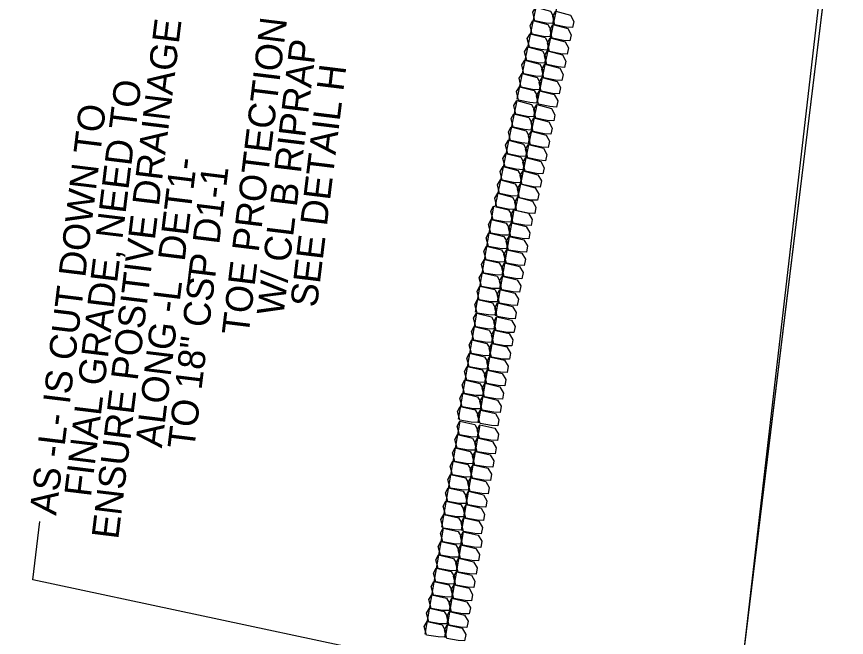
# Model space of a CAD drawing. Extents: x 465700 to 483515, y 488970 to 507540.
# Drawn here: x 481134.4 to 481288.8, y 490580.8 to 490696.3 of the extents above; entities that cross this region are included whole.
import ezdxf

# ---------------------------------------------------------------- set-up
doc = ezdxf.new("R2010")
doc.units = 0
for name, color, linetype in [('Exist Plan Preparation Watershed Blue', 7, 'Continuous'), ('Prop Earthen Structure Base Ditch Lateral Detail Label', 7, 'Continuous'), ('Prop Erosion Embankment Toe Protection CELL', 7, 'Continuous'), ('Prop Erosion Embankment Toe Protection Label', 7, 'Continuous'), ('Prop NEU Channel Block Detail Label', 7, 'Continuous')]:
    doc.layers.add(name, color=color, linetype=linetype)

msp = doc.modelspace()

# ---------------------------------------------------------------- linework, layer by layer
at = {"layer": 'Exist Plan Preparation Watershed Blue'}
for points in [[(481178.35, 489921.07), (481181.18, 489944.23), (481192.1, 489942.89), (481199.42, 490002.85), (481223.67, 490201.37), (481232.65, 490274.58), (481301.55, 490839.02), (481357.88, 490832.14), (481339.74, 490683.62), (481315.49, 490485.09), (481303.36, 490385.83), (481279.12, 490187.3), (481254.87, 489988.78), (481242.75, 489889.52)], [(480982.54, 490200.49), (481022.64, 490226.93), (481057.88, 490239.62), (481085.68, 490250.52), (481125.08, 490261.61), (481159, 490262.25), (481229.67, 490258.2), (481254.1, 490443.2), (481288.29, 490738.89), (481339.74, 490683.62), (481381.2, 490650.46), (481429.31, 490629.05), (481609.7, 490592.3), (481802.24, 490660.02), (481819.54, 490679.79), (481842.61, 490718.46), (481669.68, 490775.55), (481613.6, 490791.65)]]:
    msp.add_lwpolyline(points, dxfattribs=at)
msp.add_lwpolyline([(481259, 490360.8), (481243.71, 490365.51), (481284.29, 490697.69), (481301.55, 490839.02), (481323.3, 490836.37), (481281, 490489.23), (481265.22, 490360.1)], close=True, dxfattribs=at)
at = {"layer": 'Prop Erosion Embankment Toe Protection CELL'}
for p, q in [((481231.47, 490700.49), (481227.46, 490680.9)), ((481235.19, 490699.73), (481231.18, 490680.14)), ((481227.43, 490680.68), (481223.42, 490661.08)), ((481231.15, 490679.92), (481227.14, 490660.32)), ((481223.13, 490661.01), (481219.72, 490641.3)), ((481226.87, 490660.36), (481223.47, 490640.65)), ((481219.94, 490641.09), (481216.53, 490621.38)), ((481223.68, 490640.44), (481220.28, 490620.73)), ((481216.85, 490621.01), (481213.44, 490601.3)), ((481220.59, 490620.36), (481217.19, 490600.66)), ((481213.75, 490601.11), (481210.35, 490581.4)), ((481217.5, 490600.46), (481214.1, 490580.75))]:
    msp.add_line(p, q, dxfattribs=at)
for points in [[(481234.12, 490695), (481232.91, 490695.07), (481230.8, 490695.5), (481230.42, 490697.14), (481230.97, 490698.04), (481233.72, 490697.3), (481234.35, 490696.13), (481234.12, 490695)], [(481237.84, 490694.24), (481236.63, 490694.31), (481234.53, 490694.74), (481234.15, 490696.37), (481234.69, 490697.28), (481237.45, 490696.54), (481238.07, 490695.37), (481237.84, 490694.24)], [(481233.62, 490692.53), (481232.41, 490692.6), (481230.3, 490693.03), (481229.92, 490694.66), (481230.46, 490695.57), (481233.22, 490694.83), (481233.85, 490693.68), (481233.62, 490692.53)], [(481237.34, 490691.77), (481236.13, 490691.84), (481234.02, 490692.27), (481233.64, 490693.9), (481234.18, 490694.81), (481236.94, 490694.07), (481237.57, 490692.92), (481237.34, 490691.77)], [(481233.11, 490690.05), (481231.9, 490690.15), (481229.8, 490690.58), (481229.41, 490692.19), (481229.96, 490693.1), (481232.72, 490692.38), (481233.35, 490691.23), (481233.11, 490690.05)], [(481236.83, 490689.29), (481235.63, 490689.39), (481233.52, 490689.82), (481233.14, 490691.43), (481233.68, 490692.34), (481236.44, 490691.62), (481237.07, 490690.47), (481236.83, 490689.29)], [(481232.61, 490687.6), (481231.4, 490687.7), (481229.3, 490688.13), (481228.91, 490689.74), (481229.45, 490690.65), (481232.22, 490689.93), (481232.84, 490688.76), (481232.61, 490687.6)], [(481236.33, 490686.84), (481235.13, 490686.94), (481233.02, 490687.37), (481232.63, 490688.98), (481233.18, 490689.89), (481235.94, 490689.17), (481236.57, 490687.99), (481236.33, 490686.84)], [(481232.11, 490685.15), (481230.9, 490685.22), (481228.79, 490685.65), (481228.41, 490687.29), (481228.95, 490688.2), (481231.71, 490687.46), (481232.34, 490686.28), (481232.11, 490685.15)], [(481235.83, 490684.39), (481234.62, 490684.46), (481232.51, 490684.89), (481232.13, 490686.53), (481232.68, 490687.44), (481235.43, 490686.69), (481236.06, 490685.52), (481235.83, 490684.39)], [(481231.6, 490682.68), (481230.39, 490682.75), (481228.29, 490683.18), (481227.91, 490684.81), (481228.45, 490685.72), (481231.21, 490684.98), (481231.84, 490683.83), (481231.6, 490682.68)], [(481235.33, 490681.92), (481234.12, 490681.99), (481232.01, 490682.42), (481231.63, 490684.05), (481232.17, 490684.96), (481234.93, 490684.22), (481235.56, 490683.07), (481235.33, 490681.92)], [(481231.1, 490680.21), (481229.89, 490680.3), (481227.78, 490680.73), (481227.4, 490682.34), (481227.94, 490683.25), (481230.7, 490682.53), (481231.34, 490681.38), (481231.1, 490680.21)], [(481234.82, 490679.45), (481233.61, 490679.54), (481231.51, 490679.97), (481231.12, 490681.58), (481231.67, 490682.49), (481234.43, 490681.77), (481235.06, 490680.62), (481234.82, 490679.45)], [(481230.58, 490677.64), (481229.38, 490677.73), (481227.27, 490678.16), (481226.88, 490679.77), (481227.43, 490680.68), (481230.19, 490679.96), (481230.82, 490678.79), (481230.58, 490677.64)], [(481234.31, 490676.87), (481233.1, 490676.97), (481230.99, 490677.4), (481230.61, 490679.01), (481231.15, 490679.92), (481233.91, 490679.2), (481234.54, 490678.03), (481234.31, 490676.87)], [(481230.08, 490675.19), (481228.87, 490675.26), (481226.76, 490675.69), (481226.38, 490677.32), (481226.93, 490678.23), (481229.68, 490677.49), (481230.31, 490676.31), (481230.08, 490675.19)], [(481233.8, 490674.43), (481232.59, 490674.49), (481230.49, 490674.92), (481230.11, 490676.56), (481230.65, 490677.47), (481233.41, 490676.73), (481234.03, 490675.55), (481233.8, 490674.43)], [(481229.58, 490672.71), (481228.37, 490672.78), (481226.26, 490673.21), (481225.88, 490674.85), (481226.42, 490675.76), (481229.18, 490675.01), (481229.81, 490673.86), (481229.58, 490672.71)], [(481233.3, 490671.95), (481232.09, 490672.02), (481229.98, 490672.45), (481229.6, 490674.09), (481230.14, 490675), (481232.9, 490674.25), (481233.53, 490673.1), (481233.3, 490671.95)], [(481229.07, 490670.24), (481227.86, 490670.33), (481225.76, 490670.76), (481225.37, 490672.37), (481225.92, 490673.28), (481228.68, 490672.56), (481229.31, 490671.41), (481229.07, 490670.24)], [(481232.79, 490669.48), (481231.59, 490669.57), (481229.48, 490670), (481229.1, 490671.61), (481229.64, 490672.52), (481232.4, 490671.8), (481233.03, 490670.65), (481232.79, 490669.48)], [(481228.57, 490667.79), (481227.36, 490667.88), (481225.26, 490668.31), (481224.87, 490669.92), (481225.41, 490670.83), (481228.18, 490670.12), (481228.8, 490668.94), (481228.57, 490667.79)], [(481232.29, 490667.03), (481231.09, 490667.12), (481228.98, 490667.55), (481228.59, 490669.16), (481229.14, 490670.07), (481231.9, 490669.35), (481232.53, 490668.18), (481232.29, 490667.03)], [(481228.07, 490665.34), (481226.86, 490665.41), (481224.75, 490665.84), (481224.37, 490667.47), (481224.91, 490668.38), (481227.67, 490667.64), (481228.3, 490666.47), (481228.07, 490665.34)], [(481231.79, 490664.58), (481230.58, 490664.65), (481228.47, 490665.08), (481228.09, 490666.71), (481228.64, 490667.62), (481231.39, 490666.88), (481232.02, 490665.71), (481231.79, 490664.58)], [(481227.56, 490662.87), (481226.35, 490662.94), (481224.25, 490663.37), (481223.87, 490665), (481224.41, 490665.91), (481227.17, 490665.17), (481227.8, 490664.02), (481227.56, 490662.87)], [(481231.29, 490662.11), (481230.08, 490662.17), (481227.97, 490662.6), (481227.59, 490664.24), (481228.13, 490665.15), (481230.89, 490664.41), (481231.52, 490663.26), (481231.29, 490662.11)], [(481227.06, 490660.39), (481225.85, 490660.49), (481223.74, 490660.92), (481223.36, 490662.53), (481223.9, 490663.44), (481226.66, 490662.72), (481227.3, 490661.57), (481227.06, 490660.39)], [(481230.78, 490659.63), (481229.57, 490659.72), (481227.47, 490660.16), (481227.08, 490661.77), (481227.63, 490662.67), (481230.39, 490661.96), (481231.02, 490660.81), (481230.78, 490659.63)], [(481226.37, 490658.06), (481225.16, 490658.12), (481223.05, 490658.48), (481222.61, 490660.08), (481223.13, 490661.01), (481225.91, 490660.37), (481226.57, 490659.22), (481226.37, 490658.06)], [(481230.12, 490657.42), (481228.91, 490657.47), (481226.79, 490657.84), (481226.36, 490659.44), (481226.87, 490660.36), (481229.65, 490659.73), (481230.32, 490658.57), (481230.12, 490657.42)], [(481225.95, 490655.6), (481224.73, 490655.63), (481222.62, 490656), (481222.19, 490657.62), (481222.7, 490658.54), (481225.48, 490657.89), (481226.14, 490656.73), (481225.95, 490655.6)], [(481229.69, 490654.95), (481228.48, 490654.98), (481226.36, 490655.35), (481225.93, 490656.97), (481226.44, 490657.9), (481229.22, 490657.24), (481229.89, 490656.09), (481229.69, 490654.95)], [(481225.52, 490653.11), (481224.3, 490653.14), (481222.19, 490653.51), (481221.76, 490655.13), (481222.27, 490656.06), (481225.05, 490655.4), (481225.72, 490654.27), (481225.52, 490653.11)], [(481229.26, 490652.46), (481228.05, 490652.5), (481225.93, 490652.86), (481225.5, 490654.48), (481226.02, 490655.41), (481228.79, 490654.75), (481229.46, 490653.62), (481229.26, 490652.46)], [(481225.09, 490650.62), (481223.88, 490650.68), (481221.76, 490651.04), (481221.33, 490652.64), (481221.84, 490653.57), (481224.62, 490652.93), (481225.29, 490651.8), (481225.09, 490650.62)], [(481228.83, 490649.98), (481227.62, 490650.03), (481225.51, 490650.4), (481225.07, 490652), (481225.59, 490652.92), (481228.37, 490652.29), (481229.04, 490651.16), (481228.83, 490649.98)], [(481224.66, 490648.16), (481223.45, 490648.22), (481221.34, 490648.58), (481220.9, 490650.18), (481221.42, 490651.1), (481224.2, 490650.47), (481224.86, 490649.32), (481224.66, 490648.16)], [(481228.41, 490647.51), (481227.2, 490647.57), (481225.08, 490647.93), (481224.65, 490649.53), (481225.16, 490650.46), (481227.94, 490649.82), (481228.61, 490648.67), (481228.41, 490647.51)], [(481224.24, 490645.7), (481223.02, 490645.73), (481220.91, 490646.09), (481220.48, 490647.71), (481220.99, 490648.64), (481223.77, 490647.98), (481224.43, 490646.83), (481224.24, 490645.7)], [(481227.98, 490645.05), (481226.77, 490645.08), (481224.65, 490645.45), (481224.22, 490647.07), (481224.73, 490647.99), (481227.51, 490647.34), (481228.18, 490646.18), (481227.98, 490645.05)], [(481223.81, 490643.21), (481222.59, 490643.24), (481220.48, 490643.6), (481220.05, 490645.23), (481220.56, 490646.15), (481223.34, 490645.5), (481224.01, 490644.36), (481223.81, 490643.21)], [(481227.55, 490642.56), (481226.34, 490642.59), (481224.22, 490642.96), (481223.79, 490644.58), (481224.3, 490645.51), (481227.08, 490644.85), (481227.75, 490643.72), (481227.55, 490642.56)], [(481223.38, 490640.72), (481222.17, 490640.78), (481220.05, 490641.14), (481219.62, 490642.74), (481220.13, 490643.66), (481222.91, 490643.03), (481223.58, 490641.9), (481223.38, 490640.72)], [(481227.12, 490640.07), (481225.91, 490640.13), (481223.79, 490640.49), (481223.36, 490642.09), (481223.88, 490643.02), (481226.66, 490642.38), (481227.33, 490641.25), (481227.12, 490640.07)], [(481223.18, 490638.14), (481221.97, 490638.2), (481219.86, 490638.56), (481219.42, 490640.16), (481219.94, 490641.09), (481222.72, 490640.45), (481223.38, 490639.3), (481223.18, 490638.14)], [(481226.93, 490637.5), (481225.72, 490637.55), (481223.6, 490637.92), (481223.17, 490639.51), (481223.68, 490640.44), (481226.46, 490639.81), (481227.13, 490638.65), (481226.93, 490637.5)], [(481222.76, 490635.68), (481221.54, 490635.71), (481219.43, 490636.08), (481219, 490637.7), (481219.51, 490638.62), (481222.29, 490637.97), (481222.95, 490636.81), (481222.76, 490635.68)], [(481226.5, 490635.03), (481225.29, 490635.06), (481223.17, 490635.43), (481222.74, 490637.05), (481223.26, 490637.98), (481226.03, 490637.32), (481226.7, 490636.16), (481226.5, 490635.03)], [(481222.33, 490633.19), (481221.11, 490633.22), (481219, 490633.59), (481218.57, 490635.21), (481219.08, 490636.14), (481221.86, 490635.48), (481222.53, 490634.35), (481222.33, 490633.19)], [(481226.07, 490632.54), (481224.86, 490632.58), (481222.74, 490632.94), (481222.31, 490634.56), (481222.83, 490635.49), (481225.6, 490634.83), (481226.27, 490633.7), (481226.07, 490632.54)], [(481221.9, 490630.7), (481220.69, 490630.76), (481218.57, 490631.12), (481218.14, 490632.72), (481218.65, 490633.65), (481221.43, 490633.01), (481222.1, 490631.88), (481221.9, 490630.7)], [(481225.64, 490630.06), (481224.43, 490630.11), (481222.32, 490630.48), (481221.88, 490632.07), (481222.4, 490633), (481225.18, 490632.37), (481225.85, 490631.24), (481225.64, 490630.06)], [(481221.47, 490628.24), (481220.26, 490628.29), (481218.15, 490628.66), (481217.71, 490630.26), (481218.23, 490631.18), (481221.01, 490630.55), (481221.67, 490629.4), (481221.47, 490628.24)], [(481225.22, 490627.59), (481224.01, 490627.65), (481221.89, 490628.01), (481221.46, 490629.61), (481221.97, 490630.54), (481224.75, 490629.9), (481225.42, 490628.75), (481225.22, 490627.59)], [(481221.05, 490625.77), (481219.83, 490625.81), (481217.72, 490626.17), (481217.29, 490627.79), (481217.8, 490628.72), (481220.58, 490628.06), (481221.24, 490626.91), (481221.05, 490625.77)], [(481224.79, 490625.13), (481223.58, 490625.16), (481221.46, 490625.53), (481221.03, 490627.15), (481221.55, 490628.07), (481224.32, 490627.42), (481224.99, 490626.26), (481224.79, 490625.13)], [(481220.62, 490623.29), (481219.4, 490623.32), (481217.29, 490623.68), (481216.86, 490625.31), (481217.37, 490626.23), (481220.15, 490625.57), (481220.82, 490624.44), (481220.62, 490623.29)], [(481224.36, 490622.64), (481223.15, 490622.67), (481221.03, 490623.04), (481220.6, 490624.66), (481221.12, 490625.59), (481223.89, 490624.93), (481224.56, 490623.8), (481224.36, 490622.64)], [(481220.19, 490620.8), (481218.98, 490620.85), (481216.86, 490621.22), (481216.43, 490622.82), (481216.94, 490623.74), (481219.72, 490623.11), (481220.39, 490621.98), (481220.19, 490620.8)], [(481223.93, 490620.15), (481222.72, 490620.21), (481220.61, 490620.57), (481220.17, 490622.17), (481220.69, 490623.1), (481223.47, 490622.46), (481224.14, 490621.33), (481223.93, 490620.15)], [(481220.09, 490618.07), (481218.88, 490618.12), (481216.77, 490618.49), (481216.33, 490620.09), (481216.85, 490621.01), (481219.63, 490620.38), (481220.29, 490619.22), (481220.09, 490618.07)], [(481223.84, 490617.42), (481222.63, 490617.48), (481220.51, 490617.84), (481220.08, 490619.44), (481220.59, 490620.36), (481223.37, 490619.73), (481224.04, 490618.58), (481223.84, 490617.42)], [(481219.67, 490615.6), (481218.45, 490615.63), (481216.34, 490616), (481215.91, 490617.62), (481216.42, 490618.55), (481219.2, 490617.89), (481219.86, 490616.74), (481219.67, 490615.6)], [(481223.41, 490614.96), (481222.2, 490614.99), (481220.08, 490615.35), (481219.65, 490616.98), (481220.16, 490617.9), (481222.94, 490617.24), (481223.61, 490616.09), (481223.41, 490614.96)], [(481219.24, 490613.11), (481218.02, 490613.15), (481215.91, 490613.51), (481215.48, 490615.13), (481215.99, 490616.06), (481218.77, 490615.4), (481219.44, 490614.27), (481219.24, 490613.11)], [(481222.98, 490612.47), (481221.77, 490612.5), (481219.65, 490612.86), (481219.22, 490614.49), (481219.74, 490615.41), (481222.51, 490614.76), (481223.18, 490613.63), (481222.98, 490612.47)], [(481218.81, 490610.63), (481217.6, 490610.68), (481215.48, 490611.05), (481215.05, 490612.65), (481215.56, 490613.57), (481218.34, 490612.94), (481219.01, 490611.81), (481218.81, 490610.63)], [(481222.55, 490609.98), (481221.34, 490610.04), (481219.22, 490610.4), (481218.79, 490612), (481219.31, 490612.92), (481222.09, 490612.29), (481222.76, 490611.16), (481222.55, 490609.98)], [(481218.38, 490608.16), (481217.17, 490608.22), (481215.05, 490608.58), (481214.62, 490610.18), (481215.14, 490611.11), (481217.92, 490610.47), (481218.58, 490609.32), (481218.38, 490608.16)], [(481222.13, 490607.52), (481220.92, 490607.57), (481218.8, 490607.94), (481218.36, 490609.54), (481218.88, 490610.46), (481221.66, 490609.83), (481222.33, 490608.67), (481222.13, 490607.52)], [(481217.96, 490605.7), (481216.74, 490605.73), (481214.63, 490606.1), (481214.19, 490607.72), (481214.71, 490608.64), (481217.49, 490607.99), (481218.15, 490606.83), (481217.96, 490605.7)], [(481221.7, 490605.05), (481220.49, 490605.08), (481218.37, 490605.45), (481217.94, 490607.07), (481218.45, 490608), (481221.23, 490607.34), (481221.9, 490606.19), (481221.7, 490605.05)], [(481217.53, 490603.21), (481216.31, 490603.24), (481214.2, 490603.61), (481213.77, 490605.23), (481214.28, 490606.16), (481217.06, 490605.5), (481217.73, 490604.37), (481217.53, 490603.21)], [(481221.27, 490602.56), (481220.06, 490602.6), (481217.94, 490602.96), (481217.51, 490604.58), (481218.02, 490605.51), (481220.8, 490604.85), (481221.47, 490603.72), (481221.27, 490602.56)], [(481217.1, 490600.72), (481215.89, 490600.78), (481213.77, 490601.14), (481213.34, 490602.74), (481213.85, 490603.67), (481216.63, 490603.04), (481217.3, 490601.9), (481217.1, 490600.72)], [(481220.84, 490600.08), (481219.63, 490600.13), (481217.51, 490600.5), (481217.08, 490602.1), (481217.6, 490603.02), (481220.38, 490602.39), (481221.05, 490601.26), (481220.84, 490600.08)], [(481217, 490598.16), (481215.79, 490598.22), (481213.67, 490598.59), (481213.24, 490600.18), (481213.75, 490601.11), (481216.54, 490600.48), (481217.2, 490599.32), (481217, 490598.16)], [(481220.75, 490597.52), (481219.54, 490597.57), (481217.42, 490597.94), (481216.98, 490599.54), (481217.5, 490600.46), (481220.28, 490599.83), (481220.95, 490598.67), (481220.75, 490597.52)], [(481216.58, 490595.7), (481215.36, 490595.73), (481213.24, 490596.1), (481212.81, 490597.72), (481213.33, 490598.64), (481216.11, 490597.99), (481216.77, 490596.83), (481216.58, 490595.7)], [(481220.32, 490595.05), (481219.11, 490595.08), (481216.99, 490595.45), (481216.56, 490597.07), (481217.07, 490598), (481219.85, 490597.34), (481220.52, 490596.19), (481220.32, 490595.05)], [(481216.15, 490593.21), (481214.93, 490593.24), (481212.81, 490593.61), (481212.38, 490595.23), (481212.9, 490596.16), (481215.68, 490595.5), (481216.35, 490594.37), (481216.15, 490593.21)], [(481219.89, 490592.56), (481218.68, 490592.6), (481216.56, 490592.96), (481216.13, 490594.58), (481216.64, 490595.51), (481219.42, 490594.85), (481220.09, 490593.72), (481219.89, 490592.56)], [(481215.72, 490590.72), (481214.51, 490590.78), (481212.39, 490591.15), (481211.95, 490592.74), (481212.47, 490593.67), (481215.25, 490593.04), (481215.92, 490591.91), (481215.72, 490590.72)], [(481219.46, 490590.08), (481218.25, 490590.13), (481216.13, 490590.5), (481215.7, 490592.1), (481216.21, 490593.02), (481219, 490592.39), (481219.66, 490591.26), (481219.46, 490590.08)], [(481215.29, 490588.26), (481214.08, 490588.32), (481211.96, 490588.68), (481211.53, 490590.28), (481212.04, 490591.21), (481214.83, 490590.57), (481215.49, 490589.42), (481215.29, 490588.26)], [(481219.03, 490587.61), (481217.83, 490587.67), (481215.71, 490588.04), (481215.27, 490589.63), (481215.79, 490590.56), (481218.57, 490589.93), (481219.23, 490588.77), (481219.03, 490587.61)], [(481214.86, 490585.8), (481213.65, 490585.83), (481211.53, 490586.19), (481211.1, 490587.82), (481211.62, 490588.74), (481214.4, 490588.08), (481215.06, 490586.93), (481214.86, 490585.8)], [(481218.61, 490585.15), (481217.4, 490585.18), (481215.28, 490585.55), (481214.85, 490587.17), (481215.36, 490588.09), (481218.14, 490587.44), (481218.81, 490586.28), (481218.61, 490585.15)], [(481214.44, 490583.31), (481213.22, 490583.34), (481211.1, 490583.71), (481210.67, 490585.33), (481211.19, 490586.25), (481213.97, 490585.6), (481214.64, 490584.47), (481214.44, 490583.31)], [(481218.18, 490582.66), (481216.97, 490582.69), (481214.85, 490583.06), (481214.42, 490584.68), (481214.93, 490585.61), (481217.71, 490584.95), (481218.38, 490583.82), (481218.18, 490582.66)], [(481214.01, 490580.82), (481212.8, 490580.88), (481210.68, 490581.24), (481210.24, 490582.84), (481210.76, 490583.77), (481213.54, 490583.13), (481214.21, 490582), (481214.01, 490580.82)], [(481217.75, 490580.17), (481216.54, 490580.23), (481214.42, 490580.6), (481213.99, 490582.19), (481214.5, 490583.12), (481217.29, 490582.49), (481217.95, 490581.36), (481217.75, 490580.17)]]:
    msp.add_lwpolyline(points, dxfattribs=at)
at = {"layer": 'Prop NEU Channel Block Detail Label'}
msp.add_lwpolyline([(481291.54, 490558.67), (481137.4, 490591.51), (481138.73, 490602.35)], dxfattribs=at)

# ---------------------------------------------------------------- texts
at = {"layer": 'Prop Earthen Structure Base Ditch Lateral Detail Label'}
for s, p in [('ENSURE POSITIVE DRAINAGE ', (481153.3, 490598.92)), ('FINAL GRADE, NEED TO ', (481148.21, 490606.8)), ('AS -L- IS CUT DOWN TO', (481141.75, 490603.38)), ('ALONG -L_DET1-', (481161.42, 490615.94)), ('TO 18" CSP D1-1', (481167.43, 490615.65))]:
    msp.add_text(s, height=5, rotation=83.0394, dxfattribs=at).set_placement(p)
at = {"layer": 'Prop Erosion Embankment Toe Protection Label'}
for s, p in [('TOE PROTECTION', (481177.53, 490636.83)), ('W/ CL B RIPRAP', (481184.02, 490640.48)), ('SEE DETAIL H', (481190.26, 490642.06))]:
    msp.add_text(s, height=5, rotation=83.0365, dxfattribs=at).set_placement(p)

doc.saveas('drawing.dxf')
